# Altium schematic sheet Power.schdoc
size 307 x 182 mm
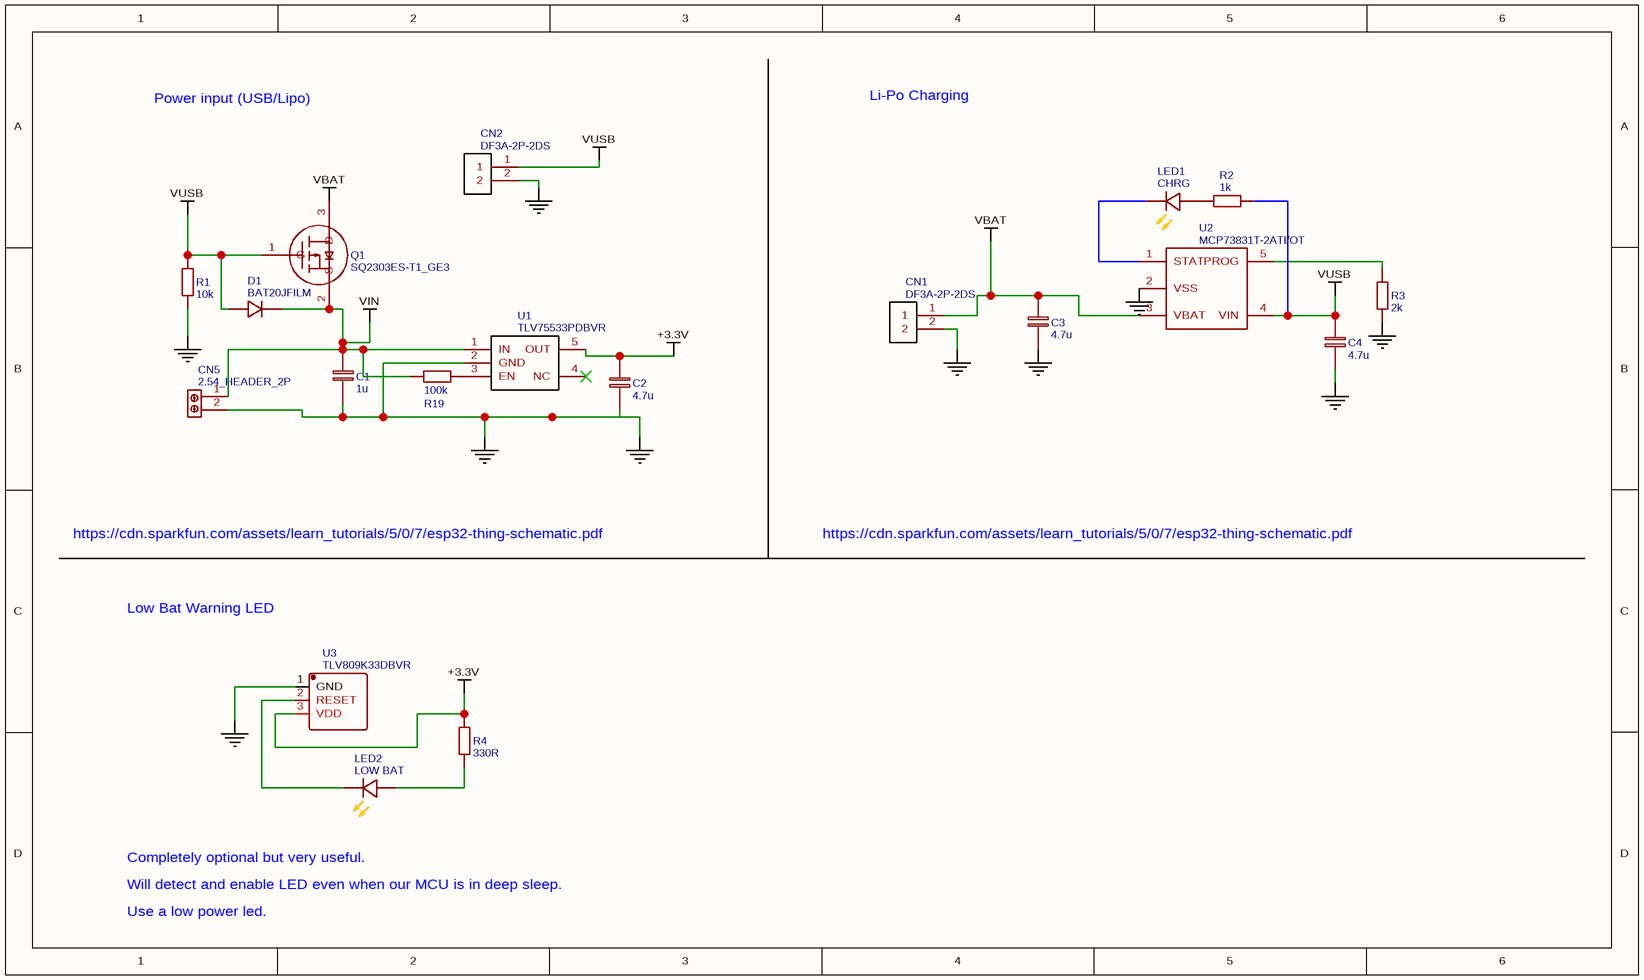
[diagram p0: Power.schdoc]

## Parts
C1  1u  [0805]
C2  4.7u  [0805]
C3  4.7u  [0805]
C4  4.7u  [0805]
CN1  DF3A-2P-2DS  [DF3A-2P-2DS]
CN2  DF3A-2P-2DS  [DF3A-2P-2DS]
CN5  2.54_HEADER_2P  [2P_2.54]
D1  BAT20JFILM  [SOD-323]
LED1  CHRG  [LED-0805]
LED2  LOW BAT  [LED-0805]
Q1  SQ2303ES-T1_GE3  [SOT-23(SOT-23-3)]
R1  10k  [0805]
R2  1k  [0805]
R3  2k  [0805]
R4  330R  [0805]
R19  100k  [0805]
U1  TLV75533PDBVR  [SOT23-5]
U2  MCP73831T-2ATI/OT  [SOT-23-5]
U3  TLV809K33DBVR  [SOT-23(SOT-23-3)]

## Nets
+3.3V: C2.1 U1.5(OUT) U3.3(VDD)
GND: C1.2 C2.2 C3.2 C4.2 CN1.2 CN2.2 CN5.2 U1.2(GND) U2.2(VSS) U3.1(GND)
VBAT: C3.1 CN1.1 Q1.3(D) U2.3(VBAT)
VIN: C1.1 CN5.1 D1.2(K) Q1.2(S) U1.1(IN)
VUSB: C4.1 CN2.1 D1.1(A) Q1.1(G) U2.4(VIN)
NetLED1_2: LED1.2(-) U2.1(STAT)
NetLED2_2: LED2.2(-) U3.2(RESET)

Not connected (* = marked no-connect by the designer): LED1 1(+); LED2 1(+); R1 1 2; R2 1 2; R3 1 2; R4 1 2; R19 1 2; U1 3(EN) 4(NC)*; U2 5(PROG)

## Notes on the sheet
- Power input (USB/Lipo)
- Li-Po Charging
- https://cdn.sparkfun.com/assets/learn_tutorials/5/0/7/esp32-thing-schematic.pdf
- Low Bat Warning LED
- Completely optional but very useful.
- Will detect and enable LED even when our MCU is in deep sleep.
- Use a low power led.
- Labels drawn without touching a wire or pin: GND

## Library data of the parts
C1 = 1u: nameAlias: Value(F)
C2-C4 = 4.7u: nameAlias: Value(F)
CN1 CN2 = DF3A-2P-2DS: Contributor: jousis
CN5 = 2.54_HEADER_2P: Contributor: Tiberius Vinczi
D1 = BAT20JFILM: BOM_Manufacturer: STMicroelectronics; Contributor: LCSC
LED1 = CHRG: BOM_Manufacturer: Hubei KENTO Elec; BOM_Manufacturer Part: 17-21SUYC/TR8
LED2 = LOW BAT: BOM_Manufacturer: Hubei KENTO Elec; BOM_Manufacturer Part: 17-21SUYC/TR8
Q1 = SQ2303ES-T1_GE3: BOM_Manufacturer: VISHAY; Contributor: LCSC
R1 = 10k: nameAlias: Value(Ω)
R2 = 1k: nameAlias: Value(Ω)
R3 = 2k: nameAlias: Value(Ω)
R4 = 330R: nameAlias: Value(Ω)
R19 = 100k: nameAlias: Value(Ω)
U1 = TLV75533PDBVR: BOM_Manufacturer: Ti; Contributor: wayneosdias
U2 = MCP73831T-2ATI/OT: BOM_Manufacturer: MICROCHIP
U3 = TLV809K33DBVR: BOM_Manufacturer: TI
